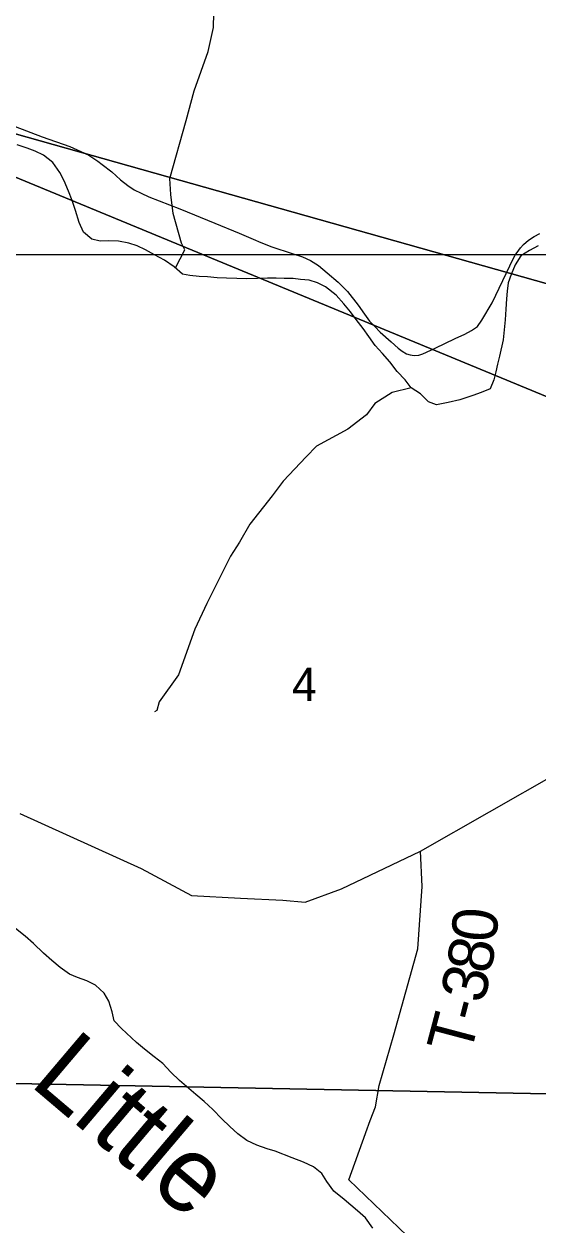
# Model space of a CAD drawing. Extents: x 0 to 34, y 0 to 22.
# Drawn here: x 5.598 to 6.245, y 15.891 to 17.402 of the extents above; entities that cross this region are included whole.
import ezdxf

# ---------------------------------------------------------------- set-up
doc = ezdxf.new("R2010")
doc.units = 0
for name, color, linetype in [('GM_X_County_Road', 7, 'Continuous'), ('GM_X_Minor_River', 7, 'Continuous'), ('GM_X_Minor_River_Text', 7, 'Continuous'), ('GM_X_Section', 7, 'Continuous'), ('GM_X_Section_Text', 7, 'Continuous'), ('GM_X_Township_Road', 7, 'Continuous'), ('GM_X_Township_Road_Text', 7, 'Continuous'), ('SC_Shading1', 7, 'Continuous'), ('SH_Data', 7, 'Continuous')]:
    doc.layers.add(name, color=color, linetype=linetype)

msp = doc.modelspace()

# ---------------------------------------------------------------- linework, layer by layer
at = {"layer": 'GM_X_County_Road'}
for p, q in [((5.5871, 17.2728), (5.621, 17.2599)), ((5.621, 17.2599), (5.6558, 17.2475)), ((5.6558, 17.2475), (5.6699, 17.2415)), ((5.6699, 17.2415), (5.6798, 17.2368)), ((5.6798, 17.2368), (5.691, 17.2293)), ((5.691, 17.2293), (5.6965, 17.2252)), ((5.6965, 17.2252), (5.7088, 17.2157)), ((5.7088, 17.2157), (5.7198, 17.2058)), ((5.7198, 17.2058), (5.7289, 17.1988)), ((5.7289, 17.1988), (5.7367, 17.1932)), ((5.7367, 17.1932), (5.7456, 17.1889)), ((5.7456, 17.1889), (5.7555, 17.1842)), ((5.7555, 17.1842), (5.7944, 17.1693)), ((5.7944, 17.1693), (5.8384, 17.1514)), ((5.8384, 17.1514), (5.8689, 17.1386)), ((5.8689, 17.1386), (5.8867, 17.1311)), ((5.8867, 17.1311), (5.8962, 17.1271)), ((5.8962, 17.1271), (5.91, 17.1215)), ((6.2268, 17.1246), (6.233, 17.1299)), ((6.233, 17.1299), (6.2402, 17.1346)), ((6.2402, 17.1346), (6.2472, 17.1381)), ((5.91, 17.1215), (5.9359, 17.1133)), ((5.9359, 17.1133), (5.9485, 17.109)), ((6.2159, 17.1105), (6.2186, 17.1145)), ((6.2186, 17.1145), (6.2228, 17.1202)), ((6.2228, 17.1202), (6.2268, 17.1246)), ((5.9485, 17.109), (5.9589, 17.1044)), ((5.9589, 17.1044), (5.9689, 17.0979)), ((5.9689, 17.0979), (5.9798, 17.0889)), ((6.1872, 17.0512), (6.2097, 17.0976)), ((6.2097, 17.0976), (6.2159, 17.1105)), ((5.9798, 17.0889), (5.9936, 17.077)), ((5.9936, 17.077), (6.0053, 17.0652)), ((6.0053, 17.0652), (6.0189, 17.048)), ((6.1745, 17.0291), (6.1872, 17.0512)), ((6.0189, 17.048), (6.0267, 17.0368)), ((6.0267, 17.0368), (6.0328, 17.0282)), ((6.0328, 17.0282), (6.0396, 17.0212)), ((6.0396, 17.0212), (6.0465, 17.0141)), ((6.1614, 17.0162), (6.169, 17.0212)), ((6.169, 17.0212), (6.1745, 17.0291)), ((6.0465, 17.0141), (6.0603, 17.0021)), ((6.1155, 16.994), (6.1407, 17.0061)), ((6.1407, 17.0061), (6.1528, 17.0116)), ((6.1528, 17.0116), (6.1614, 17.0162)), ((6.0603, 17.0021), (6.0691, 16.9942)), ((6.0691, 16.9942), (6.0743, 16.9902)), ((6.1, 16.987), (6.1155, 16.994)), ((6.0743, 16.9902), (6.0795, 16.987)), ((6.0795, 16.987), (6.084, 16.9855)), ((6.084, 16.9855), (6.0891, 16.9848)), ((6.0891, 16.9848), (6.0949, 16.9852)), ((6.0949, 16.9852), (6.1, 16.987))]:
    msp.add_line(p, q, dxfattribs=at)
at = {"layer": 'GM_X_Minor_River'}
for p, q in [((5.8365, 17.3971), (5.8374, 17.434)), ((5.8302, 17.3673), (5.8365, 17.3971)), ((5.8122, 17.3175), (5.8302, 17.3673)), ((5.8022, 17.2804), (5.8122, 17.3175)), ((5.7819, 17.2073), (5.8022, 17.2804)), ((5.6022, 17.2454), (5.5895, 17.2496)), ((5.6122, 17.2419), (5.6022, 17.2454)), ((5.623, 17.2369), (5.6122, 17.2419)), ((5.6346, 17.2277), (5.623, 17.2369)), ((5.6434, 17.2151), (5.6346, 17.2277)), ((5.6487, 17.2046), (5.6434, 17.2151)), ((5.6544, 17.1914), (5.6487, 17.2046)), ((5.783, 17.1872), (5.7819, 17.2073)), ((5.6589, 17.1797), (5.6544, 17.1914)), ((5.7861, 17.1632), (5.783, 17.1872)), ((5.6631, 17.1673), (5.6589, 17.1797)), ((5.6677, 17.1522), (5.6631, 17.1673)), ((5.7965, 17.1261), (5.7861, 17.1632)), ((5.6731, 17.1398), (5.6677, 17.1522)), ((5.6836, 17.131), (5.6731, 17.1398)), ((5.6943, 17.1287), (5.6836, 17.131)), ((5.7046, 17.129), (5.6943, 17.1287)), ((5.7171, 17.1286), (5.7046, 17.129)), ((5.7301, 17.126), (5.7171, 17.1286)), ((5.7405, 17.1229), (5.7301, 17.126)), ((5.7513, 17.1179), (5.7405, 17.1229)), ((5.7625, 17.1114), (5.7513, 17.1179)), ((5.7749, 17.1045), (5.7625, 17.1114)), ((5.7889, 17.095), (5.8008, 17.1178)), ((5.8008, 17.1178), (5.7965, 17.1261)), ((6.2345, 17.117), (6.2233, 17.1102)), ((6.2454, 17.1227), (6.2345, 17.117)), ((5.7873, 17.0965), (5.7749, 17.1045)), ((5.7975, 17.0869), (5.7873, 17.0965)), ((6.2161, 17.0989), (6.2111, 17.0866)), ((6.2233, 17.1102), (6.2161, 17.0989)), ((5.807, 17.0853), (5.7975, 17.0869)), ((5.8185, 17.0842), (5.807, 17.0853)), ((5.8291, 17.0837), (5.8185, 17.0842)), ((5.8413, 17.0826), (5.8291, 17.0837)), ((5.8531, 17.0822), (5.8413, 17.0826)), ((5.8661, 17.0815), (5.8531, 17.0822)), ((5.8786, 17.0811), (5.8661, 17.0815)), ((5.8919, 17.0815), (5.8786, 17.0811)), ((5.9045, 17.0819), (5.8919, 17.0815)), ((5.9155, 17.0822), (5.9045, 17.0819)), ((5.9258, 17.0818), (5.9155, 17.0822)), ((5.9368, 17.0818), (5.9258, 17.0818)), ((5.9463, 17.0805), (5.9368, 17.0818)), ((6.2111, 17.0866), (6.2076, 17.0762)), ((5.957, 17.0794), (5.9463, 17.0805)), ((5.9674, 17.0763), (5.957, 17.0794)), ((5.9778, 17.0712), (5.9674, 17.0763)), ((5.991, 17.0606), (5.9778, 17.0712)), ((6.2076, 17.0762), (6.2061, 17.0658)), ((6.0009, 17.0499), (5.991, 17.0606)), ((6.2052, 17.0559), (6.2045, 17.0429)), ((6.2061, 17.0658), (6.2052, 17.0559)), ((6.0092, 17.0398), (6.0009, 17.0499)), ((6.0163, 17.0302), (6.0092, 17.0398)), ((6.2045, 17.0429), (6.2037, 17.0296)), ((6.025, 17.0186), (6.0163, 17.0302)), ((6.2037, 17.0296), (6.2026, 17.0173)), ((6.0321, 17.0089), (6.025, 17.0186)), ((6.0401, 16.9974), (6.0321, 17.0089)), ((6.2026, 17.0173), (6.2011, 17.0047)), ((6.0492, 16.9874), (6.0401, 16.9974)), ((6.2011, 17.0047), (6.1964, 16.984)), ((6.0586, 16.977), (6.0492, 16.9874)), ((6.0677, 16.9647), (6.0586, 16.977)), ((6.1964, 16.984), (6.194, 16.974)), ((6.0779, 16.9544), (6.0677, 16.9647)), ((6.192, 16.9644), (6.1893, 16.9541)), ((6.194, 16.974), (6.192, 16.9644)), ((6.0855, 16.944), (6.0779, 16.9544)), ((6.1893, 16.9541), (6.1847, 16.9429)), ((6.0617, 16.9385), (6.0396, 16.9245)), ((6.0855, 16.944), (6.0617, 16.9385)), ((6.0971, 16.9367), (6.0855, 16.944)), ((6.1073, 16.9267), (6.0971, 16.9367)), ((6.1629, 16.9346), (6.1467, 16.9291)), ((6.1734, 16.9383), (6.1629, 16.9346)), ((6.1847, 16.9429), (6.1734, 16.9383)), ((6.0396, 16.9245), (6.0293, 16.9102)), ((6.1173, 16.9229), (6.1073, 16.9267)), ((6.132, 16.9256), (6.1173, 16.9229)), ((6.1467, 16.9291), (6.132, 16.9256)), ((6.0293, 16.9102), (6.0058, 16.8923)), ((6.0058, 16.8923), (5.9664, 16.8707)), ((5.9664, 16.8707), (5.9534, 16.8572)), ((5.9534, 16.8572), (5.9245, 16.8266)), ((5.9245, 16.8266), (5.9104, 16.8085)), ((5.9104, 16.8085), (5.8823, 16.7726)), ((5.8823, 16.7726), (5.8695, 16.75)), ((5.8695, 16.75), (5.858, 16.7323)), ((5.858, 16.7323), (5.8284, 16.6728)), ((5.8284, 16.6728), (5.8131, 16.6405)), ((5.8131, 16.6405), (5.7926, 16.5831)), ((5.7926, 16.5831), (5.7682, 16.5492)), ((5.7654, 16.5385), (5.7624, 16.5369)), ((5.7682, 16.5492), (5.7654, 16.5385)), ((5.5999, 16.2544), (5.5874, 16.2643)), ((5.6104, 16.2453), (5.5999, 16.2544)), ((5.623, 16.2331), (5.6104, 16.2453)), ((5.6331, 16.2239), (5.623, 16.2331)), ((5.6437, 16.2151), (5.6331, 16.2239)), ((5.6557, 16.2067), (5.6437, 16.2151)), ((5.6657, 16.2028), (5.6557, 16.2067)), ((5.6773, 16.1986), (5.6657, 16.2028)), ((5.6881, 16.1929), (5.6773, 16.1986)), ((5.699, 16.1829), (5.6881, 16.1929)), ((5.705, 16.1729), (5.699, 16.1829)), ((5.7093, 16.1593), (5.705, 16.1729)), ((5.7119, 16.1483), (5.7093, 16.1593)), ((5.7209, 16.1387), (5.7119, 16.1483)), ((5.7397, 16.121), (5.7209, 16.1387)), ((5.7499, 16.1126), (5.7397, 16.121)), ((5.762, 16.1027), (5.7499, 16.1126)), ((5.7729, 16.0943), (5.762, 16.1027)), ((5.7831, 16.0836), (5.7729, 16.0943)), ((5.7941, 16.0729), (5.7831, 16.0836)), ((5.8144, 16.0553), (5.7941, 16.0729)), ((5.8249, 16.0465), (5.8144, 16.0553)), ((5.8359, 16.0365), (5.8249, 16.0465)), ((5.8472, 16.0251), (5.8359, 16.0365)), ((5.8574, 16.0151), (5.8472, 16.0251)), ((5.8672, 16.0059), (5.8574, 16.0151)), ((5.8785, 15.9975), (5.8672, 16.0059)), ((5.8912, 15.9918), (5.8785, 15.9975)), ((5.9043, 15.9873), (5.8912, 15.9918)), ((5.9143, 15.9842), (5.9043, 15.9873)), ((5.9358, 15.9757), (5.9143, 15.9842)), ((5.9501, 15.9705), (5.9358, 15.9757)), ((5.9624, 15.9644), (5.9501, 15.9705)), ((5.973, 15.956), (5.9624, 15.9644)), ((5.9793, 15.9463), (5.973, 15.956)), ((5.9881, 15.934), (5.9793, 15.9463)), ((6.0013, 15.9234), (5.9881, 15.934)), ((6.0178, 15.909), (6.0013, 15.9234)), ((6.0279, 15.9006), (6.0178, 15.909)), ((6.037, 15.8876), (6.0279, 15.9006))]:
    msp.add_line(p, q, dxfattribs=at)
at = {"layer": 'GM_X_Section'}
for p, q in [((6.4366, 17.1114), (5.492, 17.1117)), ((5.492, 17.1117), (6.4366, 17.1114)), ((6.4161, 16.0534), (5.4597, 16.0717)), ((5.4597, 16.0717), (6.4161, 16.0534))]:
    msp.add_line(p, q, dxfattribs=at)
at = {"layer": 'GM_X_Township_Road'}
for p, q in [((6.097, 16.3616), (6.2708, 16.4605)), ((5.5932, 16.4089), (5.7455, 16.3395)), ((5.9976, 16.314), (6.097, 16.3616)), ((6.0992, 16.3171), (6.097, 16.3616)), ((5.7455, 16.3395), (5.8089, 16.3058)), ((5.9519, 16.2974), (5.9976, 16.314)), ((6.0937, 16.2387), (6.0992, 16.3171)), ((5.8089, 16.3058), (5.8707, 16.3024)), ((5.8707, 16.3024), (5.924, 16.2998)), ((5.924, 16.2998), (5.9519, 16.2974)), ((6.0638, 16.1306), (6.0937, 16.2387)), ((6.0451, 16.0667), (6.0638, 16.1306)), ((6.0404, 16.0401), (6.0451, 16.0667)), ((6.034, 16.0228), (6.0404, 16.0401)), ((6.0285, 16.0077), (6.034, 16.0228)), ((6.0071, 15.9482), (6.028, 16.0064)), ((6.028, 16.0064), (6.0285, 16.0077)), ((6.1959, 15.7676), (6.0071, 15.9482))]:
    msp.add_line(p, q, dxfattribs=at)
at = {"layer": 'SC_Shading1'}
msp.add_lwpolyline([(10.3861, 15.9111), (10.3861, 15.2276), (5.1721, 17.3806)], close=True, dxfattribs=at)
at = {"layer": 'SH_Data'}
msp.add_lwpolyline([(10.3861, 15.9111), (5.1721, 17.3806), (10.3861, 15.2276)], dxfattribs=at)

# ---------------------------------------------------------------- texts
at = {"layer": 'GM_X_Minor_River_Text'}
msp.add_text('Little', height=0.09472, rotation=319.7029, dxfattribs=at).set_placement((5.6036, 16.0685))
at = {"layer": 'GM_X_Section_Text'}
msp.add_text('4', height=0.0419, rotation=0, dxfattribs=at).set_placement((5.9355, 16.5505))
at = {"layer": 'GM_X_Township_Road_Text'}
for s, rotation, p in [('0', 84.7164, (6.1921, 16.2456)), ('8', 79.7101, (6.1851, 16.2058)), ('3', 77.0167, (6.1767, 16.1688)), ('T', 75.1914, (6.1595, 16.1032)), ('-', 75.6099, (6.1705, 16.1448))]:
    msp.add_text(s, height=0.0568, rotation=rotation, dxfattribs=at).set_placement(p)

doc.saveas('drawing.dxf')
